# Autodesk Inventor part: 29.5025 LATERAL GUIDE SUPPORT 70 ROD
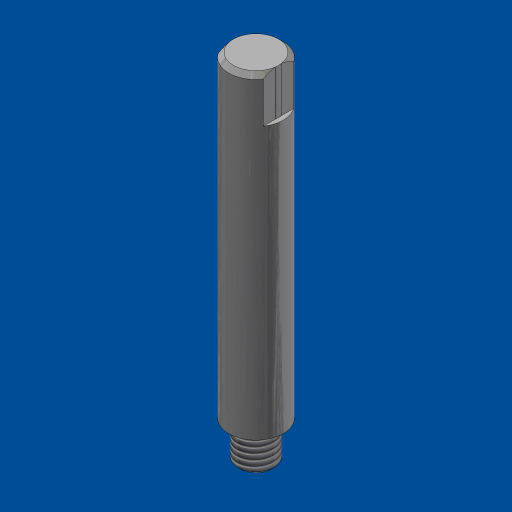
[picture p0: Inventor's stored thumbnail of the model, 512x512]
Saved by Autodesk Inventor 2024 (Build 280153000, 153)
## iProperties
Created: 2007-07
Part Number: 29.5025 LATERAL GUIDE SUPPORT 70 ROD
Material: Stainless Steel
Document SubType Name: Modeling
Designer: Andy Moles
Density: 8.08 g/cm^3
Appearance: Steel
Author: Andy Moles
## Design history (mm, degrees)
sketch "Sketch1"
  geometry: C1 r 6 at (0, 0); 1 further point
  constraints: 1 centre point, 1 coincident
  dimensions: "d0" = 12 diameter of C1
extrude "Extrusion1" new body sketch "Sketch1" distance "d1" = 70; taper "d2" = 0 deg
chamfer "Chamfer1" distance "d3" = 1; stored, may be unused: second distance "d4" = 2, angle "d5" = 45 deg
sketch "Sketch2"
  geometry: C1 r 6 at (0, 0) reference; C2 r 4 at (0, 0)
  constraints: 1 centre point, 1 coincident
  dimensions: "d6" = 8 diameter of C2
extrude "Extrusion2" join sketch "Sketch2" distance "d7" = 8; taper "d8" = 0 deg
thread "Thread1" dims "d9" = 10, "d10" = 0
chamfer "Chamfer2" distance "d11" = 0.5; stored, may be unused: second distance "d12" = 2, angle "d13" = 45 deg
sketch "Sketch3"
  geometry: L1 (-9.929, -12.869)-(-4.95, -12.869); L2 (-4.95, -12.869)-(-4.95, 9.45); L3 (-4.95, 9.45)-(-9.929, 9.45); L4 (-9.929, 9.45)-(-9.929, -12.869); L5 (4.95, -12.869)-(13.034, -12.869); L6 (13.034, -12.869)-(13.034, 9.04); L7 (13.034, 9.04)-(4.95, 9.04); L8 (4.95, 9.04)-(4.95, -12.869); C1 r 5 at (0, 0) reference; C2 r 6 at (0, 0) reference; 8 further points
  constraints: 16 end point, 4 parallel, 2 horizontal, 2 perpendicular, 1 point on line
  dimensions: "d14" = 9.9 distance between parallel lines of L2 L8; "d15" = 12 diameter of C2 (derived); "d16" = 1.05 distance edge to line of C2 L8
extrude "Extrusion3" cut sketch "Sketch3" distance "d17" = 10; taper "d18" = 0 deg
body "Solid1"
